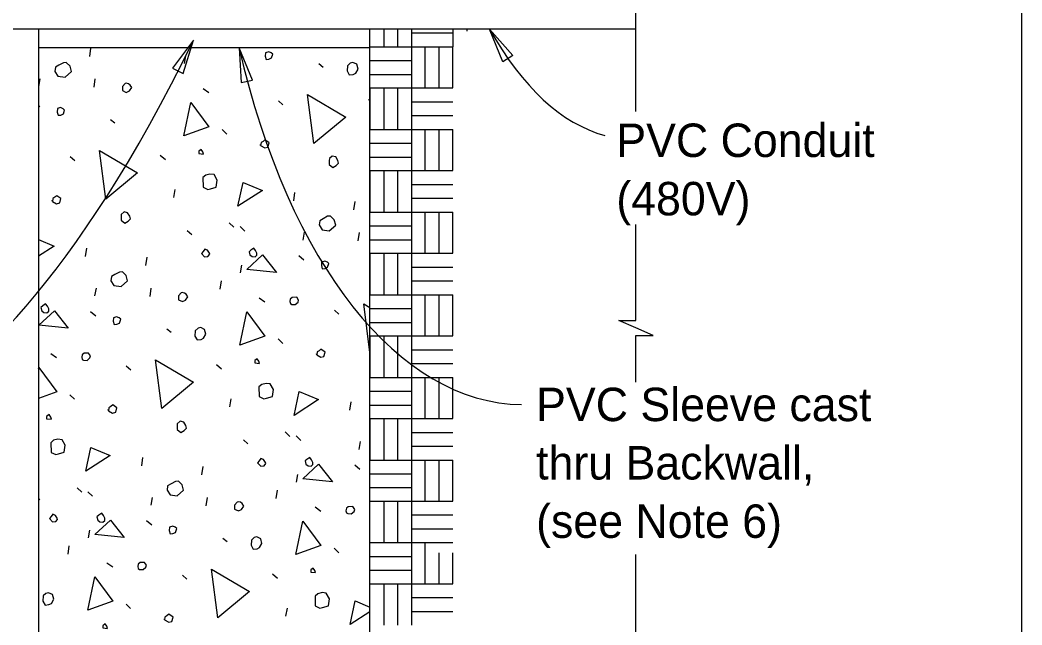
# Model space of a CAD drawing. Extents: x 112544 to 112597.1, y 111084 to 111107.1.
# Drawn here: x 112570.246 to 112574.78, y 111089.924 to 111092.66 of the extents above; entities that cross this region are included whole.
import ezdxf

# ---------------------------------------------------------------- set-up
doc = ezdxf.new("R2010")
doc.units = 0
for name, color, linetype in [('ActivePts-ConstElements', 7, 'Continuous'), ('Dimension', 7, 'Continuous'), ('Lighting', 7, 'Continuous'), ('Miscellaneous', 7, 'Continuous'), ('SupstrConc', 7, 'Continuous')]:
    doc.layers.add(name, color=color, linetype=linetype)

msp = doc.modelspace()

# ---------------------------------------------------------------- linework, layer by layer
at = {"layer": 'ActivePts-ConstElements'}
msp.add_lwpolyline([(112543.9918, 111085.9039), (112574.7797, 111085.9039), (112574.7797, 111105.3634), (112543.9918, 111105.3634)], close=True, dxfattribs=at)
at = {"layer": 'Dimension'}
for points in [[(112573.0332, 111092.2463), (112573.0332, 111094.5328)], [(112573.0332, 111091.0228), (112573.0332, 111091.2341), (112573.1107, 111091.2341), (112573.0332, 111091.2678), (112572.9557, 111091.3016), (112573.0332, 111091.3016), (112573.0332, 111091.7354)], [(112573.0332, 111088.0729), (112573.0332, 111090.2426)]]:
    msp.add_lwpolyline(points, dxfattribs=at)
for points in [[(112572.3711, 111092.6186), (112572.4758, 111092.4997), (112572.4307, 111092.4718)], [(112571.0307, 111092.5697), (112570.9365, 111092.4423), (112570.9837, 111092.4184)], [(112571.2378, 111092.5353), (112571.2469, 111092.3771), (112571.2985, 111092.3889)]]:
    msp.add_lwpolyline(points, close=True, dxfattribs=at)
for centre, major_axis, ratio, start_param, end_param in [((112573.1162, 111094.4875), (0.1111, 2.3674), 0.464296, 2.502126, 3.038691), ((112572.5396, 111093.685), (0.0241, 2.7636), 0.515084, 2.004362, 3.141607)]:
    msp.add_ellipse(centre, major_axis=major_axis, ratio=ratio, start_param=start_param, end_param=end_param, dxfattribs=at)
msp.add_open_spline([(112566.5718, 111090.0345), (112566.9987, 111090.0346), (112567.8381, 111090.0387), (112568.5158, 111090.2156), (112569.5419, 111090.6383), (112570.4976, 111091.4736), (112571.0308, 111092.5697)], degree=3, dxfattribs=at)
at = {"layer": 'Lighting'}
msp.add_line((112573.0332, 111092.6186), (112569.9743, 111092.6186), dxfattribs=at)
at = {"layer": 'Miscellaneous'}
for p, q in [((112571.8922, 111092.6186), (112571.8922, 111092.5392)), ((112571.9547, 111092.6186), (112571.9547, 111092.5392)), ((112572.0185, 111092.5392), (112572.0185, 111092.6186)), ((112572.0185, 111092.6017), (112572.2047, 111092.6017)), ((112572.2047, 111092.6186), (112572.2047, 111092.5392)), ((112572.2672, 111092.6186), (112572.2672, 111092.6097)), ((112571.8297, 111092.5353), (112570.3297, 111092.5353)), ((112570.5618, 111092.4961), (112570.5672, 111092.5337)), ((112570.9899, 111092.4632), (112570.996, 111092.4985)), ((112571.8297, 111092.5392), (112572.0185, 111092.5392)), ((112572.0185, 111092.1655), (112572.0185, 111092.5392)), ((112572.0185, 111092.5392), (112572.2047, 111092.5392)), ((112572.0797, 111092.353), (112572.0797, 111092.5392)), ((112572.1422, 111092.353), (112572.1422, 111092.5392)), ((112572.2047, 111092.353), (112572.2047, 111092.5392)), ((112571.5981, 111092.4632), (112571.6178, 111092.4477)), ((112571.8297, 111092.4767), (112572.0185, 111092.4767)), ((112571.8297, 111092.4142), (112572.0185, 111092.4142)), ((112570.3318, 111092.3594), (112570.3379, 111092.3947)), ((112570.5811, 111092.3563), (112570.5866, 111092.394)), ((112571.0742, 111092.3513), (112571.1, 111092.3323)), ((112571.8297, 111092.353), (112572.2047, 111092.353)), ((112571.8297, 111092.353), (112571.8297, 111092.1655)), ((112571.8922, 111092.353), (112571.8922, 111092.1655)), ((112571.9547, 111092.353), (112571.9547, 111092.1655)), ((112570.3297, 111092.2743), (112570.3352, 111092.2697)), ((112571.4154, 111092.2951), (112571.4357, 111092.2773)), ((112571.8228, 111092.3008), (112571.8297, 111092.295)), ((112572.0185, 111092.2905), (112572.2047, 111092.2905)), ((112572.0185, 111092.228), (112572.2047, 111092.228)), ((112570.6563, 111092.2108), (112570.676, 111092.1954)), ((112571.1605, 111092.1647), (112571.1814, 111092.1444)), ((112571.8297, 111092.1655), (112572.0185, 111092.1655)), ((112572.0185, 111092.1655), (112572.2047, 111092.1655)), ((112572.0185, 111091.7917), (112572.0185, 111092.1655)), ((112572.0797, 111091.9792), (112572.0797, 111092.1655)), ((112572.1422, 111091.9792), (112572.1422, 111092.1655)), ((112572.2047, 111091.9792), (112572.2047, 111092.1655)), ((112571.8297, 111092.103), (112572.0185, 111092.103)), ((112570.4736, 111092.0428), (112570.4939, 111092.0249)), ((112570.881, 111092.0484), (112570.9044, 111092.0288)), ((112571.8297, 111092.0405), (112572.0185, 111092.0405)), ((112571.8297, 111091.9792), (112572.2047, 111091.9792)), ((112571.8297, 111091.9792), (112571.8297, 111091.7917)), ((112571.8922, 111091.9792), (112571.8922, 111091.7917)), ((112571.9547, 111091.9792), (112571.9547, 111091.7917)), ((112572.0185, 111091.9167), (112572.2047, 111091.9167)), ((112570.9424, 111091.8578), (112570.9485, 111091.8931)), ((112571.4848, 111091.8427), (112571.4903, 111091.8804)), ((112571.7572, 111091.8018), (112571.7626, 111091.8395)), ((112572.0185, 111091.8542), (112572.2047, 111091.8542)), ((112571.8297, 111091.7916), (112572.0185, 111091.7916)), ((112572.0185, 111091.7917), (112572.2047, 111091.7917)), ((112572.0185, 111091.4179), (112572.0185, 111091.7916)), ((112572.0797, 111091.6054), (112572.0797, 111091.7916)), ((112572.1422, 111091.6054), (112572.1422, 111091.7916)), ((112572.2047, 111091.6054), (112572.2047, 111091.7916)), ((112571.193, 111091.7438), (112571.214, 111091.7235)), ((112571.2418, 111091.7258), (112571.2628, 111091.7055)), ((112571.8297, 111091.7291), (112572.0185, 111091.7291)), ((112571.0032, 111091.7085), (112571.0235, 111091.6906)), ((112571.5273, 111091.6651), (112571.5333, 111091.7004)), ((112571.7765, 111091.662), (112571.782, 111091.6997)), ((112571.8297, 111091.6666), (112572.0185, 111091.6666)), ((112570.5431, 111091.5903), (112570.5485, 111091.628)), ((112571.5072, 111091.595), (112571.5306, 111091.5754)), ((112571.8297, 111091.6054), (112572.2047, 111091.6054)), ((112571.8297, 111091.6054), (112571.8297, 111091.4179)), ((112571.8922, 111091.6054), (112571.8922, 111091.4179)), ((112571.9547, 111091.6054), (112571.9547, 111091.4179)), ((112570.8154, 111091.5494), (112570.8209, 111091.5871)), ((112571.2435, 111091.5166), (112571.2496, 111091.5519)), ((112572.0185, 111091.5429), (112572.2047, 111091.5429)), ((112571.152, 111091.4429), (112571.1574, 111091.4806)), ((112572.0185, 111091.4804), (112572.2047, 111091.4804)), ((112570.5855, 111091.4128), (112570.5916, 111091.448)), ((112570.8348, 111091.4097), (112570.8402, 111091.4474)), ((112571.8297, 111091.4179), (112572.0185, 111091.4179)), ((112572.0185, 111091.0441), (112572.0185, 111091.4179)), ((112572.0185, 111091.4179), (112572.2047, 111091.4179)), ((112572.0797, 111091.2316), (112572.0797, 111091.4179)), ((112572.1422, 111091.2316), (112572.1422, 111091.4179)), ((112572.2047, 111091.2316), (112572.2047, 111091.4179)), ((112571.3279, 111091.4046), (112571.3537, 111091.3857)), ((112570.5654, 111091.3427), (112570.5888, 111091.3231)), ((112571.669, 111091.3485), (112571.6893, 111091.3307)), ((112571.8297, 111091.3554), (112572.0185, 111091.3554)), ((112571.8297, 111091.2929), (112572.0185, 111091.2929)), ((112570.91, 111091.2642), (112570.9297, 111091.2488)), ((112571.8297, 111091.2316), (112572.2047, 111091.2316)), ((112571.8297, 111091.2316), (112571.8297, 111091.0441)), ((112571.8922, 111091.2316), (112571.8922, 111091.0441)), ((112571.9547, 111091.2316), (112571.9547, 111091.0441)), ((112571.4141, 111091.2181), (112571.4351, 111091.1978)), ((112570.3861, 111091.1523), (112570.4119, 111091.1333)), ((112572.0185, 111091.1691), (112572.2047, 111091.1691)), ((112570.7272, 111091.0962), (112570.7476, 111091.0783)), ((112571.1347, 111091.1018), (112571.158, 111091.0822)), ((112572.0185, 111091.1066), (112572.2047, 111091.1066)), ((112571.8297, 111091.0441), (112572.0185, 111091.0441)), ((112572.0185, 111090.6704), (112572.0185, 111091.0441)), ((112572.0185, 111091.0441), (112572.2047, 111091.0441)), ((112572.0797, 111090.8579), (112572.0797, 111091.0441)), ((112572.1422, 111090.8579), (112572.1422, 111091.0441)), ((112572.2047, 111090.8579), (112572.2047, 111091.0441)), ((112570.4723, 111090.9658), (112570.4933, 111090.9455)), ((112571.8297, 111090.9816), (112572.0185, 111090.9816)), ((112571.1961, 111090.9112), (112571.2022, 111090.9465)), ((112571.7385, 111090.8961), (112571.7439, 111090.9338)), ((112571.8297, 111090.9191), (112572.0185, 111090.9191)), ((112571.8297, 111090.8579), (112572.2047, 111090.8579)), ((112571.8297, 111090.8579), (112571.8297, 111090.6704)), ((112571.8922, 111090.8579), (112571.8922, 111090.6704)), ((112571.9547, 111090.8579), (112571.9547, 111090.6704)), ((112571.4466, 111090.7972), (112571.4676, 111090.7769)), ((112571.4955, 111090.7792), (112571.5164, 111090.7589)), ((112572.0185, 111090.7954), (112572.2047, 111090.7954)), ((112571.2568, 111090.7619), (112571.2771, 111090.744)), ((112571.7809, 111090.7185), (112571.787, 111090.7538)), ((112572.0185, 111090.7329), (112572.2047, 111090.7329)), ((112570.7967, 111090.6437), (112570.8021, 111090.6814)), ((112571.0691, 111090.6028), (112571.0745, 111090.6405)), ((112571.7608, 111090.6484), (112571.7842, 111090.6288)), ((112571.8297, 111090.6704), (112572.0185, 111090.6704)), ((112572.0185, 111090.6704), (112572.2047, 111090.6704)), ((112572.0185, 111090.2966), (112572.0185, 111090.6704)), ((112572.0797, 111090.4841), (112572.0797, 111090.6704)), ((112572.1422, 111090.4841), (112572.1422, 111090.6704)), ((112572.2047, 111090.4841), (112572.2047, 111090.6704)), ((112571.4972, 111090.57), (112571.5032, 111090.6053)), ((112571.8297, 111090.6079), (112572.0185, 111090.6079)), ((112570.5049, 111090.5448), (112570.5258, 111090.5246)), ((112570.5537, 111090.5269), (112570.5746, 111090.5066)), ((112570.8391, 111090.4662), (112570.8452, 111090.5014)), ((112571.4056, 111090.4963), (112571.411, 111090.534)), ((112571.8297, 111090.5454), (112572.0185, 111090.5454)), ((112570.3297, 111090.4966), (112570.3354, 111090.4917)), ((112571.0884, 111090.4631), (112571.0938, 111090.5008)), ((112571.5815, 111090.458), (112571.6073, 111090.4391)), ((112571.8297, 111090.4841), (112572.2047, 111090.4841)), ((112571.8922, 111090.4841), (112571.8922, 111090.2966)), ((112571.9547, 111090.4841), (112571.9547, 111090.2966)), ((112572.0185, 111090.4217), (112572.2048, 111090.4217)), ((112570.8191, 111090.3961), (112570.8424, 111090.3765)), ((112570.5554, 111090.3177), (112570.5615, 111090.3529)), ((112572.0185, 111090.3592), (112572.2048, 111090.3592)), ((112570.4638, 111090.244), (112570.4693, 111090.2817)), ((112571.1636, 111090.3176), (112571.1833, 111090.3022)), ((112571.8297, 111090.2966), (112572.0185, 111090.2966)), ((112572.0185, 111090.2967), (112572.2048, 111090.2967)), ((112572.0185, 111089.9229), (112572.0185, 111090.2966)), ((112572.0797, 111090.1104), (112572.0797, 111090.2966)), ((112571.6677, 111090.2715), (112571.6887, 111090.2512)), ((112571.8297, 111090.2341), (112572.0185, 111090.2341)), ((112572.1422, 111090.1104), (112572.1422, 111090.2507)), ((112572.2047, 111090.1104), (112572.2047, 111090.2507)), ((112570.6397, 111090.2057), (112570.6655, 111090.1867)), ((112570.9809, 111090.1496), (112571.0012, 111090.1317)), ((112571.3883, 111090.1552), (112571.4117, 111090.1356)), ((112571.8297, 111090.1716), (112572.0185, 111090.1716)), ((112571.8297, 111090.1104), (112572.2047, 111090.1104)), ((112571.8922, 111090.1104), (112571.8922, 111089.9229)), ((112571.9547, 111090.1104), (112571.9547, 111089.9229)), ((112570.726, 111090.0191), (112570.7469, 111089.9989)), ((112572.0185, 111090.0479), (112572.2047, 111090.0479)), ((112571.4497, 111089.9646), (112571.4558, 111089.9999)), ((112572.0185, 111089.9854), (112572.2047, 111089.9854))]:
    msp.add_line(p, q, dxfattribs=at)
for points in [[(112571.3562, 111092.4967), (112571.3601, 111092.4822), (112571.3728, 111092.483), (112571.3842, 111092.4887), (112571.39, 111092.5057), (112571.3832, 111092.5117), (112571.3716, 111092.5164), (112571.3571, 111092.5125), (112571.3562, 111092.4967)], [(112570.4041, 111092.4279), (112570.4178, 111092.4057), (112570.45, 111092.4014), (112570.4793, 111092.4274), (112570.4728, 111092.4515), (112570.4555, 111092.4676), (112570.4428, 111092.4668), (112570.4224, 111092.4561), (112570.4068, 111092.4468), (112570.4041, 111092.4279)], [(112571.7274, 111092.4538), (112571.726, 111092.4301), (112571.736, 111092.4121), (112571.7536, 111092.4142), (112571.765, 111092.4199), (112571.7756, 111092.4382), (112571.7698, 111092.46), (112571.7521, 111092.4682), (112571.74, 111092.4649), (112571.7274, 111092.4538)], [(112570.7096, 111092.3597), (112570.7093, 111092.3415), (112570.7271, 111092.3333), (112570.7409, 111092.3396), (112570.7521, 111092.3555), (112570.7441, 111092.3663), (112570.7373, 111092.3723), (112570.7264, 111092.3745), (112570.7215, 111092.3732), (112570.7096, 111092.3597)], [(112571.5757, 111092.1026), (112571.5477, 111092.3228), (112571.7198, 111092.2214), (112571.5757, 111092.1026)], [(112570.9869, 111092.1363), (112571.0189, 111092.2873), (112571.1002, 111092.177), (112570.9869, 111092.1363)], [(112570.4144, 111092.2443), (112570.4183, 111092.2298), (112570.431, 111092.2307), (112570.4425, 111092.2363), (112570.4482, 111092.2534), (112570.4415, 111092.2593), (112570.4299, 111092.264), (112570.4154, 111092.2601), (112570.4144, 111092.2443)], [(112571.3351, 111092.0925), (112571.3535, 111092.0818), (112571.368, 111092.0857), (112571.3731, 111092.1052), (112571.3541, 111092.1182), (112571.3457, 111092.1108), (112571.3367, 111092.1058), (112571.3351, 111092.0925), (112571.3338, 111092.0973)], [(112570.6339, 111091.8502), (112570.6059, 111092.0705), (112570.7781, 111091.9691), (112570.6339, 111091.8502)], [(112571.0549, 111092.0562), (112571.0762, 111092.0541), (112571.0736, 111092.0638), (112571.0655, 111092.0746), (112571.0548, 111092.0665), (112571.0549, 111092.0562)], [(112571.6455, 111092.0255), (112571.6452, 111092.0073), (112571.6618, 111091.9936), (112571.6774, 111092.003), (112571.6876, 111092.0135), (112571.6843, 111092.0256), (112571.675, 111092.0412), (112571.6585, 111092.0445), (112571.646, 111092.0334), (112571.6455, 111092.0255)], [(112571.0738, 111091.9474), (112571.0751, 111091.9037), (112571.0959, 111091.8938), (112571.108, 111091.897), (112571.1345, 111091.9041), (112571.1388, 111091.9363), (112571.1245, 111091.961), (112571.1056, 111091.9637), (112571.0863, 111091.9585), (112571.0738, 111091.9474)], [(112571.2324, 111091.819), (112571.2554, 111091.9262), (112571.3428, 111091.89), (112571.2324, 111091.819)], [(112570.3933, 111091.8401), (112570.4117, 111091.8295), (112570.4262, 111091.8334), (112570.4313, 111091.8529), (112570.4123, 111091.8659), (112570.4039, 111091.8585), (112570.3949, 111091.8535), (112570.3933, 111091.8401), (112570.392, 111091.8449)], [(112570.7037, 111091.7732), (112570.7034, 111091.755), (112570.72, 111091.7413), (112570.7356, 111091.7507), (112570.7458, 111091.7611), (112570.7425, 111091.7732), (112570.7332, 111091.7888), (112570.7168, 111091.7922), (112570.7042, 111091.7811), (112570.7037, 111091.7732)], [(112571.5995, 111091.7337), (112571.6132, 111091.7114), (112571.6454, 111091.7071), (112571.6747, 111091.7331), (112571.6682, 111091.7572), (112571.651, 111091.7733), (112571.6382, 111091.7725), (112571.6178, 111091.7619), (112571.6022, 111091.7525), (112571.5995, 111091.7337)], [(112570.3297, 111091.6672), (112570.401, 111091.6377), (112570.3297, 111091.5918)], [(112571.0674, 111091.604), (112571.0816, 111091.5897), (112571.0967, 111091.5912), (112571.1044, 111091.601), (112571.1031, 111091.6058), (112571.0944, 111091.619), (112571.0828, 111091.6237), (112571.0751, 111091.6139), (112571.0674, 111091.604)], [(112571.273, 111091.5323), (112571.3434, 111091.5977), (112571.406, 111091.5188), (112571.273, 111091.5323)], [(112571.2864, 111091.598), (112571.2963, 111091.5903), (112571.3096, 111091.5887), (112571.318, 111091.5961), (112571.3178, 111091.6064), (112571.3122, 111091.6178), (112571.3041, 111091.6286), (112571.2909, 111091.6199), (112571.2825, 111091.6125), (112571.2864, 111091.598)], [(112571.6098, 111091.5501), (112571.6137, 111091.5356), (112571.6264, 111091.5364), (112571.6379, 111091.5421), (112571.6436, 111091.5591), (112571.6369, 111091.5651), (112571.6253, 111091.5697), (112571.6108, 111091.5659), (112571.6098, 111091.5501)], [(112570.6577, 111091.4813), (112570.6714, 111091.4591), (112570.7036, 111091.4548), (112570.7329, 111091.4807), (112570.7264, 111091.5049), (112570.7092, 111091.521), (112570.6965, 111091.5202), (112570.676, 111091.5095), (112570.6604, 111091.5001), (112570.6577, 111091.4813)], [(112570.9633, 111091.4131), (112570.963, 111091.3949), (112570.9807, 111091.3867), (112570.9945, 111091.393), (112571.0058, 111091.4089), (112570.9977, 111091.4197), (112570.991, 111091.4257), (112570.98, 111091.4279), (112570.9752, 111091.4266), (112570.9633, 111091.4131)], [(112570.3446, 111091.3457), (112570.3545, 111091.3379), (112570.3678, 111091.3363), (112570.3762, 111091.3438), (112570.376, 111091.3541), (112570.3704, 111091.3655), (112570.3623, 111091.3763), (112570.3491, 111091.3676), (112570.3408, 111091.3601), (112570.3446, 111091.3457)], [(112571.4696, 111091.3779), (112571.4757, 111091.3744), (112571.4915, 111091.3734), (112571.5041, 111091.3846), (112571.507, 111091.3931), (112571.4983, 111091.4063), (112571.4776, 111091.406), (112571.4693, 111091.3985), (112571.467, 111091.3876), (112571.4696, 111091.3779)], [(112571.8293, 111091.156), (112571.8014, 111091.3762), (112571.8297, 111091.3595)], [(112570.3312, 111091.2799), (112570.4016, 111091.3454), (112570.4642, 111091.2664), (112570.3312, 111091.2799)], [(112570.6681, 111091.2977), (112570.6719, 111091.2832), (112570.6847, 111091.2841), (112570.6961, 111091.2897), (112570.7019, 111091.3068), (112570.6951, 111091.3127), (112570.6835, 111091.3174), (112570.669, 111091.3135), (112570.6681, 111091.2977)], [(112571.2405, 111091.1897), (112571.2726, 111091.3406), (112571.3539, 111091.2304), (112571.2405, 111091.1897)], [(112571.0393, 111091.2549), (112571.0379, 111091.2312), (112571.0479, 111091.2132), (112571.0654, 111091.2153), (112571.0769, 111091.2209), (112571.0875, 111091.2393), (112571.0817, 111091.261), (112571.0639, 111091.2692), (112571.0519, 111091.266), (112571.0393, 111091.2549)], [(112570.5278, 111091.1256), (112570.534, 111091.122), (112570.5498, 111091.1211), (112570.5623, 111091.1322), (112570.5652, 111091.1408), (112570.5565, 111091.1539), (112570.5359, 111091.1536), (112570.5275, 111091.1462), (112570.5253, 111091.1352), (112570.5278, 111091.1256)], [(112571.5887, 111091.1458), (112571.6071, 111091.1352), (112571.6216, 111091.1391), (112571.6267, 111091.1586), (112571.6077, 111091.1716), (112571.5994, 111091.1642), (112571.5903, 111091.1592), (112571.5887, 111091.1458), (112571.5875, 111091.1507)], [(112571.8297, 111091.1563), (112571.8293, 111091.156)], [(112570.8875, 111090.9036), (112570.8596, 111091.1239), (112571.0317, 111091.0225), (112570.8875, 111090.9036)], [(112571.3086, 111091.1096), (112571.3298, 111091.1075), (112571.3273, 111091.1172), (112571.3192, 111091.128), (112571.3084, 111091.1199), (112571.3086, 111091.1096)], [(112570.3297, 111091.0832), (112570.3308, 111091.0883), (112570.4121, 111090.9781), (112570.3297, 111090.9485)], [(112571.3274, 111091.0008), (112571.3287, 111090.9571), (112571.3495, 111090.9472), (112571.3616, 111090.9504), (112571.3882, 111090.9575), (112571.3925, 111090.9897), (112571.3781, 111091.0143), (112571.3593, 111091.0171), (112571.3399, 111091.0119), (112571.3274, 111091.0008)], [(112571.486, 111090.8724), (112571.5091, 111090.9796), (112571.5964, 111090.9434), (112571.486, 111090.8724)], [(112570.647, 111090.8935), (112570.6653, 111090.8829), (112570.6798, 111090.8868), (112570.685, 111090.9063), (112570.6659, 111090.9193), (112570.6576, 111090.9119), (112570.6486, 111090.9069), (112570.647, 111090.8935), (112570.6457, 111090.8983)], [(112570.3668, 111090.8572), (112570.3881, 111090.8552), (112570.3855, 111090.8648), (112570.3774, 111090.8756), (112570.3666, 111090.8676), (112570.3668, 111090.8572)], [(112570.9574, 111090.8266), (112570.9571, 111090.8084), (112570.9737, 111090.7947), (112570.9893, 111090.804), (112570.9994, 111090.8145), (112570.9962, 111090.8266), (112570.9868, 111090.8422), (112570.9704, 111090.8456), (112570.9578, 111090.8344), (112570.9574, 111090.8266)], [(112570.3856, 111090.7484), (112570.387, 111090.7048), (112570.4077, 111090.6948), (112570.4198, 111090.698), (112570.4464, 111090.7052), (112570.4507, 111090.7374), (112570.4363, 111090.762), (112570.4175, 111090.7647), (112570.3982, 111090.7595), (112570.3856, 111090.7484)], [(112570.5442, 111090.6201), (112570.5673, 111090.7272), (112570.6546, 111090.6911), (112570.5442, 111090.6201)], [(112571.321, 111090.6574), (112571.3352, 111090.6431), (112571.3504, 111090.6446), (112571.3581, 111090.6544), (112571.3568, 111090.6592), (112571.3481, 111090.6724), (112571.3365, 111090.6771), (112571.3288, 111090.6672), (112571.321, 111090.6574)], [(112571.5266, 111090.5857), (112571.5971, 111090.6511), (112571.6596, 111090.5721), (112571.5266, 111090.5857)], [(112571.5401, 111090.6514), (112571.5499, 111090.6437), (112571.5633, 111090.6421), (112571.5716, 111090.6495), (112571.5715, 111090.6598), (112571.5658, 111090.6712), (112571.5577, 111090.682), (112571.5445, 111090.6733), (112571.5362, 111090.6659), (112571.5401, 111090.6514)], [(112570.9113, 111090.5347), (112570.9251, 111090.5125), (112570.9573, 111090.5082), (112570.9865, 111090.5341), (112570.9801, 111090.5583), (112570.9628, 111090.5744), (112570.9501, 111090.5736), (112570.9297, 111090.5629), (112570.9141, 111090.5535), (112570.9113, 111090.5347)], [(112571.2169, 111090.4665), (112571.2166, 111090.4483), (112571.2343, 111090.4401), (112571.2482, 111090.4464), (112571.2594, 111090.4623), (112571.2514, 111090.4731), (112571.2446, 111090.4791), (112571.2336, 111090.4813), (112571.2288, 111090.48), (112571.2169, 111090.4665)], [(112571.7233, 111090.4313), (112571.7294, 111090.4278), (112571.7452, 111090.4268), (112571.7577, 111090.438), (112571.7606, 111090.4465), (112571.7519, 111090.4597), (112571.7313, 111090.4593), (112571.7229, 111090.4519), (112571.7207, 111090.441), (112571.7233, 111090.4313)], [(112570.3793, 111090.4051), (112570.3935, 111090.3907), (112570.4086, 111090.3922), (112570.4163, 111090.402), (112570.415, 111090.4069), (112570.4063, 111090.4201), (112570.3947, 111090.4247), (112570.387, 111090.4149), (112570.3793, 111090.4051)], [(112570.5983, 111090.399), (112570.6081, 111090.3913), (112570.6215, 111090.3897), (112570.6298, 111090.3972), (112570.6297, 111090.4075), (112570.624, 111090.4189), (112570.616, 111090.4297), (112570.6028, 111090.421), (112570.5944, 111090.4135), (112570.5983, 111090.399)], [(112570.5848, 111090.3333), (112570.6553, 111090.3988), (112570.7179, 111090.3198), (112570.5848, 111090.3333)], [(112570.9217, 111090.3511), (112570.9256, 111090.3366), (112570.9383, 111090.3375), (112570.9497, 111090.3431), (112570.9555, 111090.3602), (112570.9487, 111090.3661), (112570.9371, 111090.3708), (112570.9227, 111090.3669), (112570.9217, 111090.3511)], [(112571.4942, 111090.2431), (112571.5262, 111090.394), (112571.6075, 111090.2838), (112571.4942, 111090.2431)], [(112571.293, 111090.3082), (112571.2915, 111090.2846), (112571.3015, 111090.2665), (112571.3191, 111090.2687), (112571.3305, 111090.2743), (112571.3411, 111090.2927), (112571.3353, 111090.3144), (112571.3176, 111090.3226), (112571.3055, 111090.3194), (112571.293, 111090.3082)], [(112570.7815, 111090.179), (112570.7876, 111090.1754), (112570.8034, 111090.1745), (112570.8159, 111090.1856), (112570.8188, 111090.1941), (112570.8101, 111090.2073), (112570.7895, 111090.207), (112570.7811, 111090.1996), (112570.7789, 111090.1886), (112570.7815, 111090.179)], [(112570.5524, 111089.9908), (112570.5844, 111090.1417), (112570.6657, 111090.0315), (112570.5524, 111089.9908)], [(112571.1412, 111089.957), (112571.1132, 111090.1773), (112571.2853, 111090.0759), (112571.1412, 111089.957)], [(112571.5622, 111090.163), (112571.5835, 111090.1609), (112571.5809, 111090.1706), (112571.5728, 111090.1814), (112571.5621, 111090.1733), (112571.5622, 111090.163)], [(112570.3512, 111090.0559), (112570.3498, 111090.0322), (112570.3598, 111090.0142), (112570.3773, 111090.0163), (112570.3887, 111090.022), (112570.3993, 111090.0403), (112570.3935, 111090.0621), (112570.3758, 111090.0703), (112570.3637, 111090.067), (112570.3512, 111090.0559)], [(112571.581, 111090.0541), (112571.5824, 111090.0105), (112571.6032, 111090.0005), (112571.6152, 111090.0038), (112571.6418, 111090.0109), (112571.6461, 111090.0431), (112571.6317, 111090.0677), (112571.6129, 111090.0705), (112571.5936, 111090.0653), (112571.581, 111090.0541)], [(112571.7397, 111089.9258), (112571.7627, 111090.0329), (112571.8297, 111090.0052)], [(112570.9006, 111089.9469), (112570.919, 111089.9363), (112570.9335, 111089.9402), (112570.9386, 111089.9597), (112570.9196, 111089.9727), (112570.9112, 111089.9653), (112570.9022, 111089.9603), (112570.9006, 111089.9469), (112570.8993, 111089.9517)], [(112571.8297, 111089.9837), (112571.7397, 111089.9258)], [(112570.6204, 111089.9106), (112570.6417, 111089.9086), (112570.6391, 111089.9182), (112570.6311, 111089.929), (112570.6203, 111089.9209), (112570.6204, 111089.9106)]]:
    msp.add_lwpolyline(points, dxfattribs=at)
at = {"layer": 'SupstrConc'}
for p, q in [((112570.3297, 111092.6186), (112570.3297, 111088.1505)), ((112571.8297, 111088.1504), (112571.8297, 111092.6186))]:
    msp.add_line(p, q, dxfattribs=at)

# ---------------------------------------------------------------- texts
at = {"layer": 'Dimension'}
for s, p in [('PVC Conduit', (112572.9443, 111092.0409)), ('(480V)', (112572.9443, 111091.7769)), ('PVC Sleeve cast', (112572.5814, 111090.8462)), ('thru Backwall,', (112572.5814, 111090.5822)), ('(see Note 6)', (112572.5814, 111090.3182))]:
    msp.add_text(s, height=0.1512, dxfattribs=at).set_placement(p)

doc.saveas('drawing.dxf')
